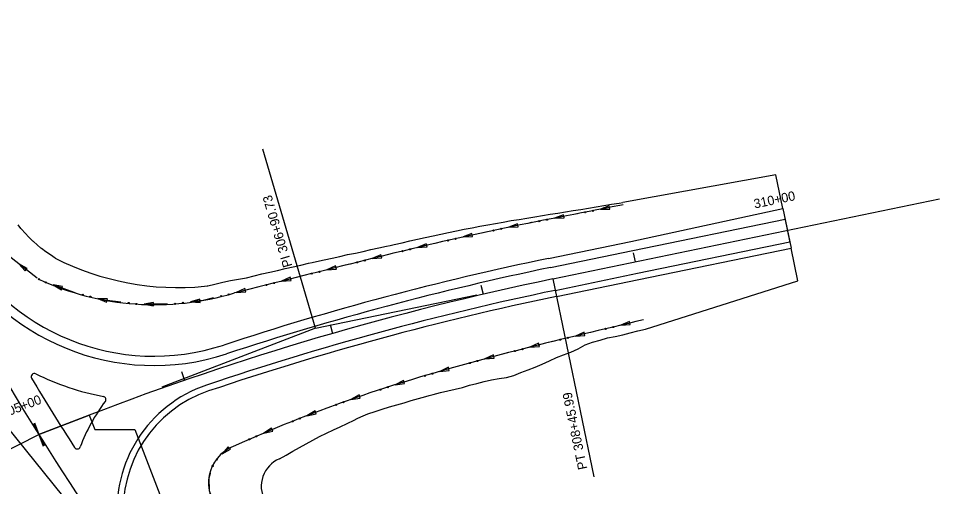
# Model space of a CAD drawing. Extents: x 916431 to 921570, y 1763982 to 1768032.
# Drawn here: x 918689 to 919282, y 1765530 to 1765831 of the extents above; entities that cross this region are included whole.
import ezdxf

# ---------------------------------------------------------------- set-up
doc = ezdxf.new("R2010")
doc.units = 0
for name, color, linetype in [('R_Horz Alg', 7, 'Continuous'), ('R_Horz Alg Annot', 7, 'Continuous'), ('R_Horz Alg Stationing', 7, 'Continuous'), ('R_Proposed Const Limits', 7, 'Continuous'), ('R_Proposed Road', 7, 'Continuous'), ('R_Shld', 7, 'Continuous'), ('R_Special Ditch', 7, 'Continuous')]:
    doc.layers.add(name, color=color, linetype=linetype)

msp = doc.modelspace()

# ---------------------------------------------------------------- linework, layer by layer
at = {"layer": 'R_Horz Alg'}
for p, q in [((919033.19, 1765663.38), (919281.92, 1765714.9)), ((919033.19, 1765663.38), (919281.92, 1765714.9)), ((918734.93, 1765575.77), (918702.47, 1765563.28)), ((918702.47, 1765563.28), (918734.93, 1765575.77)), ((918519.58, 1765470.12), (918702.47, 1765563.28))]:
    msp.add_line(p, q, dxfattribs=at)
for centre, radius, start, end in [((920196.91, 1766498.5), 1762.95, 202.25028, 218.97694), ((919420.56, 1763793.22), 1909.86, 101.70222, 111.03833), ((919420.56, 1763793.22), 1909.86, 101.70222, 111.03833)]:
    msp.add_arc(centre, radius, start, end, dxfattribs=at)
at = {"layer": 'R_Horz Alg Annot'}
for p, q in [((918880.48, 1765631.75), (918984.23, 1765653.24)), ((918880.48, 1765631.75), (918781.6, 1765593.72)), ((918663.37, 1765591.08), (918777.08, 1765450.54)), ((918738.47, 1765566.58), (918764.29, 1765566.55))]:
    msp.add_line(p, q, dxfattribs=at)
for points in [[(918880.48, 1765631.75), (918846.66, 1765746.89)], [(919033.19, 1765663.38), (919059.56, 1765536.08)], [(918734.93, 1765575.77), (918738.47, 1765566.58)], [(918764.29, 1765566.55), (918803.28, 1765465.17)]]:
    msp.add_lwpolyline(points, dxfattribs=at)
at = {"layer": 'R_Horz Alg Stationing'}
for points in [[(919182.38, 1765702.45), (919185.63, 1765686.78)], [(919084.86, 1765680.21), (919086.08, 1765674.34)], [(918986.92, 1765659.36), (918988.28, 1765653.51)], [(918889.85, 1765634.1), (918891.51, 1765628.34)], [(918794.23, 1765603.81), (918796.19, 1765598.14)], [(918698.84, 1765570.41), (918706.1, 1765556.15)], [(918698.84, 1765570.41), (918706.1, 1765556.15)], [(918699.6, 1765570.75), (918705.34, 1765555.81)]]:
    msp.add_lwpolyline(points, dxfattribs=at)
at = {"layer": 'R_Proposed Const Limits'}
for points in [[(919181.08, 1765708.75), (919176.59, 1765730.4), (919078.16, 1765712.56)], [(918809.02, 1765658.63), (918810.71, 1765658.93), (918811.18, 1765659.01), (918815.77, 1765659.98), (918820.76, 1765661.25), (918825.76, 1765662.47), (918830.88, 1765663.32), (918835.98, 1765664.19), (918840.99, 1765665.39), (918845.99, 1765666.57), (918851, 1765667.74), (918856, 1765668.9), (918861.02, 1765670.02), (918866.05, 1765671.1), (918871.05, 1765672.26), (918876.05, 1765673.42), (918878.36, 1765673.96), (918881.06, 1765674.54), (918886.08, 1765675.61), (918891.09, 1765676.73), (918896.08, 1765677.88), (918901.09, 1765679.01), (918906.11, 1765680.05), (918911.12, 1765681.13), (918916.11, 1765682.28), (918921.11, 1765683.41), (918926.13, 1765684.42), (918928.46, 1765684.89), (918931.15, 1765685.45), (918936.13, 1765686.63), (918941.12, 1765687.79), (918946.1, 1765688.95), (918951.09, 1765690.1), (918956.09, 1765691.2), (918961.09, 1765692.26), (918966.11, 1765693.29), (918971.12, 1765694.32), (918976.13, 1765695.35), (918981.16, 1765696.31), (918986.19, 1765697.24), (918991.22, 1765698.16), (918996.25, 1765699.09), (919001.29, 1765700), (919006.33, 1765700.86), (919011.38, 1765701.69), (919016.43, 1765702.49), (919021.48, 1765703.31), (919026.48, 1765704.17), (919031.43, 1765704.94), (919036.37, 1765705.72), (919041.3, 1765706.59), (919046.25, 1765707.36), (919051.19, 1765708.14), (919056.14, 1765708.91), (919061.08, 1765709.69), (919066.01, 1765710.57), (919070.94, 1765711.38), (919075.89, 1765712.16), (919078.16, 1765712.56)], [(918712.98, 1765676.7), (918709.98, 1765678.79), (918707, 1765680.88), (918704.12, 1765683.06), (918703.88, 1765683.26), (918701.35, 1765685.34), (918698.96, 1765687.44), (918698.67, 1765687.71), (918697.62, 1765688.69), (918696.93, 1765689.35), (918696.09, 1765690.17), (918693.64, 1765692.74), (918691.36, 1765695.44), (918691.02, 1765695.87), (918689.16, 1765698.2)], [(919092.67, 1765631.15), (919190.74, 1765662.1), (919186.38, 1765683.16)], [(918857.26, 1765547.56), (918861.53, 1765550.06), (918865.81, 1765552.55), (918870.12, 1765554.93), (918874.46, 1765557.27), (918878.76, 1765559.72), (918883.12, 1765562), (918887.54, 1765564.12), (918891.97, 1765566.21), (918896.41, 1765568.28), (918900.86, 1765570.33), (918905.29, 1765572.46), (918907.32, 1765573.5), (918909.69, 1765574.71), (918914.2, 1765576.56), (918918.82, 1765578.06), (918923.44, 1765579.57), (918928.04, 1765581.16), (918932.74, 1765582.38), (918937.4, 1765583.74), (918942.06, 1765585.12), (918946.73, 1765586.45), (918951.4, 1765587.77), (918953.57, 1765588.37), (918956.08, 1765589.06), (918960.78, 1765590.29), (918965.51, 1765591.39), (918970.25, 1765592.47), (918974.97, 1765593.61), (918979.62, 1765595.01), (918984.33, 1765596.2), (918989.05, 1765597.36), (918993.78, 1765598.47), (918998.59, 1765599.23), (919003.4, 1765599.98), (919008.06, 1765601.35), (919012.63, 1765603.18), (919017.24, 1765604.81), (919021.82, 1765606.64), (919026.35, 1765608.64), (919030.89, 1765610.68), (919035.4, 1765612.87), (919040.02, 1765614.58), (919044.7, 1765616.22), (919049.33, 1765618.5), (919053.94, 1765620.89), (919058.66, 1765622.78), (919063.52, 1765623.94), (919068.31, 1765625.48), (919073.22, 1765626.41), (919078.13, 1765627.36), (919082.97, 1765628.68), (919087.82, 1765629.9), (919092.67, 1765631.15)]]:
    msp.add_lwpolyline(points, dxfattribs=at)
for centre, radius, start, end in [((918792.18, 1765833.37), 175.55, 243.17977, 275.50176), ((918864.61, 1765529.99), 19.05, 112.67795, 208.20547)]:
    msp.add_arc(centre, radius, start, end, dxfattribs=at)
at = {"layer": 'R_Proposed Road'}
for p, q in [((919181.08, 1765708.75), (919186.38, 1765683.16)), ((919084.56, 1765681.68), (919182.49, 1765701.93)), ((919087.6, 1765666.99), (919185.52, 1765687.28)), ((919031.67, 1765670.72), (919084.56, 1765681.68)), ((919034.71, 1765656.04), (919087.6, 1765666.99))]:
    msp.add_line(p, q, dxfattribs=at)
for centre, radius, start, end in [((918776.54, 1765757.7), 150, 207.5444, 288.15084), ((919420.56, 1763793.22), 1917.36, 101.70222, 108.15084), ((919420.56, 1763793.22), 1902.36, 101.70222, 108.70584), ((918699.58, 1765600.53), 2, 63.91293, 210.9518), ((918776.54, 1765757.7), 173, 243.91293, 259.1681), ((920196.91, 1766498.5), 1747.95, 210.9518, 212.67226), ((918837.71, 1765514.58), 85, 108.70584, 185.72161), ((918837.71, 1765514.58), 116, 142.86085, 159.45924), ((918743.65, 1765585.82), 2, 322.86085, 79.1681), ((918727.22, 1765555.98), 2, 212.67226, 339.45924)]:
    msp.add_arc(centre, radius, start, end, dxfattribs=at)
at = {"layer": 'R_Shld'}
for p, q in [((919083.34, 1765687.55), (919181.08, 1765708.75)), ((919030.45, 1765676.6), (919083.34, 1765687.55)), ((919088.41, 1765663.07), (919186.38, 1765683.16)), ((919035.52, 1765652.12), (919088.41, 1765663.07))]:
    msp.add_line(p, q, dxfattribs=at)
for centre, radius, start, end in [((918776.54, 1765757.7), 144, 207.5444, 288.15084), ((919420.56, 1763793.22), 1923.36, 101.70222, 108.15084), ((919420.56, 1763793.22), 1898.36, 101.70222, 108.70584), ((918837.71, 1765514.58), 81, 108.70584, 185.00335)]:
    msp.add_arc(centre, radius, start, end, dxfattribs=at)
at = {"layer": 'R_Special Ditch'}
for p, q in [((919069.44, 1765710.39), (919063.75, 1765708.2)), ((919069.84, 1765708.31), (919069.44, 1765710.39)), ((919039.95, 1765704.66), (919034.26, 1765702.48)), ((919040.35, 1765702.58), (919039.95, 1765704.66)), ((919063.75, 1765708.2), (919069.84, 1765708.31)), ((919010.47, 1765698.87), (919004.8, 1765696.64)), ((919004.8, 1765696.64), (919010.89, 1765696.79)), ((919010.89, 1765696.79), (919010.47, 1765698.87)), ((919034.26, 1765702.48), (919040.35, 1765702.58)), ((918981.06, 1765692.68), (918975.42, 1765690.36)), ((918981.51, 1765690.61), (918981.06, 1765692.68)), ((918951.75, 1765686.03), (918946.15, 1765683.62)), ((918952.23, 1765683.97), (918951.75, 1765686.03)), ((918975.42, 1765690.36), (918981.51, 1765690.61)), ((918946.15, 1765683.62), (918952.23, 1765683.97)), ((918689.7, 1765673.06), (918693.77, 1765668.53)), ((918695.08, 1765670.19), (918689.7, 1765673.06)), ((918922.54, 1765678.95), (918916.97, 1765676.48)), ((918916.97, 1765676.48), (918923.05, 1765676.89)), ((918923.05, 1765676.89), (918922.54, 1765678.95)), ((918693.77, 1765668.53), (918695.08, 1765670.19)), ((918893.39, 1765671.71), (918887.82, 1765669.24)), ((918887.82, 1765669.24), (918893.9, 1765669.66)), ((918893.9, 1765669.66), (918893.39, 1765671.71)), ((918864.24, 1765664.44), (918858.68, 1765661.96)), ((918858.68, 1765661.96), (918864.76, 1765662.39)), ((918864.76, 1765662.39), (918864.24, 1765664.44)), ((918711.75, 1765659.49), (918717.03, 1765656.46)), ((918717.75, 1765658.45), (918711.75, 1765659.49)), ((918717.03, 1765656.46), (918717.75, 1765658.45)), ((918835.1, 1765657.14), (918829.54, 1765654.65)), ((918835.62, 1765655.09), (918835.1, 1765657.14)), ((918740.47, 1765650.89), (918746.07, 1765648.48)), ((918746.56, 1765650.54), (918740.47, 1765650.89)), ((918746.07, 1765648.48), (918746.56, 1765650.54)), ((918806, 1765650.36), (918800.16, 1765648.61)), ((918806.24, 1765648.26), (918806, 1765650.36)), ((918829.54, 1765654.65), (918835.62, 1765655.09)), ((918776.21, 1765648.18), (918770.21, 1765647.11)), ((918770.21, 1765647.11), (918776.21, 1765646.06)), ((918776.21, 1765646.06), (918776.21, 1765648.18)), ((918800.16, 1765648.61), (918806.24, 1765648.26)), ((919082.44, 1765636.02), (919076.85, 1765633.6)), ((919076.85, 1765633.6), (919082.93, 1765633.96)), ((919082.93, 1765633.96), (919082.44, 1765636.02)), ((919053.22, 1765629.06), (919047.63, 1765626.64)), ((919047.63, 1765626.64), (919053.71, 1765627)), ((919053.71, 1765627), (919053.22, 1765629.06)), ((919024.01, 1765622), (919018.45, 1765619.52)), ((919018.45, 1765619.52), (919024.52, 1765619.95)), ((919024.52, 1765619.95), (919024.01, 1765622)), ((918994.9, 1765614.51), (918989.38, 1765611.94)), ((918995.45, 1765612.47), (918994.9, 1765614.51)), ((918989.38, 1765611.94), (918995.45, 1765612.47)), ((918965.92, 1765606.55), (918960.44, 1765603.89)), ((918960.44, 1765603.89), (918966.5, 1765604.51)), ((918966.5, 1765604.51), (918965.92, 1765606.55)), ((918937.08, 1765598.08), (918931.66, 1765595.29)), ((918931.66, 1765595.29), (918937.71, 1765596.06)), ((918937.71, 1765596.06), (918937.08, 1765598.08)), ((918908.48, 1765588.77), (918903.16, 1765585.8)), ((918903.16, 1765585.8), (918909.18, 1765586.77)), ((918909.18, 1765586.77), (918908.48, 1765588.77)), ((918880.2, 1765578.56), (918874.98, 1765575.42)), ((918880.96, 1765576.58), (918880.2, 1765578.56)), ((918874.98, 1765575.42), (918880.96, 1765576.58)), ((918852.25, 1765567.45), (918847.13, 1765564.15)), ((918853.08, 1765565.5), (918852.25, 1765567.45)), ((918847.13, 1765564.15), (918853.08, 1765565.5)), ((918824.35, 1765555.48), (918820.36, 1765550.88)), ((918825.69, 1765553.84), (918824.35, 1765555.48)), ((918820.36, 1765550.88), (918825.69, 1765553.84))]:
    msp.add_line(p, q, dxfattribs=at)
for points in [[(919078.47, 1765711.06), (919076.21, 1765710.62), (919071.3, 1765709.67), (919066.39, 1765708.72), (919061.48, 1765707.76), (919056.57, 1765706.81), (919051.66, 1765705.86), (919046.75, 1765704.9), (919041.85, 1765703.95), (919036.94, 1765703), (919032.03, 1765702.04), (919027.12, 1765701.09), (919022.15, 1765700.12), (919017.14, 1765699.13), (919012.14, 1765698.13), (919007.14, 1765697.11), (919002.15, 1765696.08), (918997.15, 1765695.04), (918992.16, 1765693.99), (918987.17, 1765692.92), (918982.19, 1765691.84), (918977.2, 1765690.75), (918972.22, 1765689.64), (918967.25, 1765688.52), (918962.27, 1765687.39), (918957.3, 1765686.24), (918952.33, 1765685.08), (918947.36, 1765683.91), (918942.4, 1765682.72), (918937.44, 1765681.52), (918932.48, 1765680.31), (918929.82, 1765679.66), (918927.53, 1765679.09), (918922.57, 1765677.86), (918917.62, 1765676.64), (918912.66, 1765675.41), (918907.71, 1765674.18), (918902.75, 1765672.95), (918897.8, 1765671.72), (918892.84, 1765670.49), (918887.89, 1765669.25), (918882.93, 1765668.02), (918880.26, 1765667.35), (918877.97, 1765666.78), (918873.01, 1765665.54), (918868.05, 1765664.31), (918863.09, 1765663.07), (918858.13, 1765661.83), (918853.17, 1765660.58), (918848.21, 1765659.34), (918843.24, 1765658.09), (918838.28, 1765656.85), (918833.31, 1765655.6), (918828.34, 1765654.35)], [(919078.47, 1765711.06), (919076.21, 1765710.62), (919071.3, 1765709.67), (919066.39, 1765708.72), (919063.75, 1765708.2)], [(919048.99, 1765705.34), (919046.75, 1765704.9), (919041.85, 1765703.95), (919036.94, 1765703), (919034.26, 1765702.48)], [(919049.02, 1765705.34), (919048.99, 1765705.34)], [(919019.5, 1765699.6), (919017.14, 1765699.13), (919012.14, 1765698.13), (919007.14, 1765697.11), (919004.8, 1765696.63)], [(919019.54, 1765699.6), (919019.5, 1765699.6)], [(918990.08, 1765693.54), (918987.17, 1765692.92), (918982.19, 1765691.84), (918977.2, 1765690.75), (918975.42, 1765690.35)], [(918990.12, 1765693.55), (918990.08, 1765693.54)], [(918960.76, 1765687.04), (918957.3, 1765686.24), (918952.33, 1765685.08), (918947.36, 1765683.91), (918946.15, 1765683.62)], [(918960.79, 1765687.05), (918960.76, 1765687.04)], [(918931.54, 1765680.08), (918929.82, 1765679.66), (918927.53, 1765679.09), (918922.57, 1765677.86), (918917.62, 1765676.64), (918916.97, 1765676.48)], [(918931.57, 1765680.09), (918931.54, 1765680.08)], [(918701.52, 1765663.82), (918682.87, 1765678.39)], [(918701.52, 1765663.82), (918689.7, 1765673.06)], [(918902.38, 1765672.86), (918897.8, 1765671.72), (918892.84, 1765670.49), (918887.89, 1765669.25), (918887.82, 1765669.24)], [(918902.42, 1765672.87), (918902.38, 1765672.86)], [(918702.42, 1765663.25), (918702.42, 1765663.25)], [(918873.23, 1765665.6), (918873.01, 1765665.54), (918868.05, 1765664.31), (918863.09, 1765663.07), (918858.68, 1765661.96)], [(918873.27, 1765665.61), (918873.23, 1765665.6)], [(918725.85, 1765654.39), (918711.75, 1765659.49)], [(918844.09, 1765658.31), (918843.24, 1765658.09), (918838.28, 1765656.85), (918833.31, 1765655.6), (918829.54, 1765654.65)], [(918844.13, 1765658.32), (918844.09, 1765658.31)], [(918725.89, 1765654.38), (918725.85, 1765654.39)], [(918755.25, 1765648.46), (918746.49, 1765649.47), (918740.47, 1765650.89)], [(918814.92, 1765651.15), (918808.23, 1765649.56), (918800.16, 1765648.61)], [(918814.96, 1765651.16), (918814.92, 1765651.15)], [(918755.29, 1765648.46), (918755.25, 1765648.46)], [(918785.21, 1765647.13), (918770.21, 1765647.11)], [(918785.25, 1765647.13), (918785.21, 1765647.13)], [(919091.44, 1765637.08), (919086.57, 1765635.92), (919081.71, 1765634.76), (919076.84, 1765633.6), (919071.98, 1765632.44), (919067.11, 1765631.28), (919062.24, 1765630.12), (919057.38, 1765628.96), (919052.51, 1765627.8), (919047.65, 1765626.64), (919042.78, 1765625.48), (919037.98, 1765624.33), (919033.22, 1765623.18), (919028.46, 1765622.01), (919023.71, 1765620.84), (919018.96, 1765619.64), (919014.21, 1765618.44), (919009.46, 1765617.23), (919004.72, 1765616), (918999.98, 1765614.76), (918995.25, 1765613.51), (918990.52, 1765612.24), (918985.8, 1765610.97), (918981.07, 1765609.68), (918976.35, 1765608.38), (918971.64, 1765607.06), (918966.93, 1765605.74), (918962.22, 1765604.4), (918957.52, 1765603.05), (918952.82, 1765601.69), (918950.29, 1765600.95), (918948.12, 1765600.31), (918943.44, 1765598.91), (918938.76, 1765597.49), (918934.08, 1765596.04), (918929.42, 1765594.57), (918924.76, 1765593.08), (918920.11, 1765591.56), (918915.46, 1765590.02), (918910.83, 1765588.45), (918906.2, 1765586.86), (918903.72, 1765585.99), (918901.58, 1765585.24), (918896.97, 1765583.61), (918892.37, 1765581.95), (918887.78, 1765580.26), (918883.2, 1765578.55), (918878.62, 1765576.82), (918874.05, 1765575.06), (918869.5, 1765573.28), (918864.95, 1765571.48), (918860.41, 1765569.65), (918855.88, 1765567.8), (918851.36, 1765565.93), (918846.85, 1765564.03), (918842.77, 1765562.29), (918842.36, 1765562.11), (918840.87, 1765561.47), (918837.87, 1765560.17), (918833.39, 1765558.21), (918828.92, 1765556.22), (918824.46, 1765554.21)], [(919091.44, 1765637.08), (919086.57, 1765635.92), (919081.71, 1765634.76), (919076.85, 1765633.6)], [(919062.22, 1765630.12), (919057.38, 1765628.96), (919052.51, 1765627.8), (919047.65, 1765626.64), (919047.63, 1765626.64)], [(919062.26, 1765630.12), (919062.24, 1765630.12), (919062.22, 1765630.12)], [(919033.01, 1765623.13), (919028.46, 1765622.01), (919023.71, 1765620.84), (919018.96, 1765619.64), (919018.45, 1765619.52)], [(919033.04, 1765623.14), (919033.01, 1765623.13)], [(919003.88, 1765615.78), (918999.98, 1765614.76), (918995.25, 1765613.51), (918990.52, 1765612.24), (918989.38, 1765611.93)], [(919003.92, 1765615.79), (919003.88, 1765615.78)], [(918974.88, 1765607.96), (918971.64, 1765607.06), (918966.93, 1765605.74), (918962.22, 1765604.4), (918960.44, 1765603.89)], [(918974.91, 1765607.97), (918974.88, 1765607.96)], [(918946.01, 1765599.68), (918943.44, 1765598.91), (918938.76, 1765597.49), (918934.08, 1765596.04), (918931.67, 1765595.28)], [(918946.04, 1765599.69), (918946.01, 1765599.68)], [(918917.36, 1765590.65), (918915.46, 1765590.02), (918910.83, 1765588.45), (918906.2, 1765586.86), (918903.72, 1765585.99), (918903.16, 1765585.8)], [(918917.4, 1765590.66), (918917.36, 1765590.65)], [(918889.01, 1765580.71), (918887.78, 1765580.26), (918883.2, 1765578.55), (918878.62, 1765576.82), (918874.98, 1765575.42)], [(918889.05, 1765580.73), (918889.01, 1765580.71)], [(918860.99, 1765569.89), (918860.41, 1765569.65), (918855.88, 1765567.8), (918851.36, 1765565.93), (918847.13, 1765564.15)], [(918861.03, 1765569.9), (918860.99, 1765569.89)], [(918833.33, 1765558.18), (918828.92, 1765556.22), (918824.46, 1765554.21), (918820.36, 1765550.88)], [(918833.37, 1765558.2), (918833.33, 1765558.18)], [(918812.74, 1765538.29), (918811.82, 1765535.12), (918812.02, 1765527.25), (918813.25, 1765523.63)], [(918812.75, 1765538.33), (918812.74, 1765538.29)]]:
    msp.add_lwpolyline(points, dxfattribs=at)
for centre in [(919053.92, 1765706.26), (919058.84, 1765707.21), (919024.44, 1765700.53), (919029.35, 1765701.49), (918995, 1765694.55), (918999.9, 1765695.58), (918965.66, 1765688.12), (918970.55, 1765689.22), (918936.42, 1765681.24), (918941.29, 1765682.42), (918907.26, 1765674.03), (918912.12, 1765675.24), (918878.11, 1765666.78), (918882.97, 1765667.99), (918702.45, 1765663.2), (918707.03, 1765661.16), (918848.97, 1765659.49), (918853.83, 1765660.71), (918730.71, 1765653.15), (918735.59, 1765652), (918819.81, 1765652.28), (918824.69, 1765653.44), (918760.24, 1765647.85), (918765.21, 1765647.28), (918790.22, 1765647.4), (918795.19, 1765647.98), (919067.11, 1765631.24), (919071.99, 1765632.41), (919042.77, 1765625.44), (919037.9, 1765624.27), (919008.75, 1765617), (919013.6, 1765618.25), (918979.73, 1765609.27), (918984.56, 1765610.59), (918955.64, 1765602.47), (918950.83, 1765601.07), (918922.14, 1765592.18), (918926.91, 1765593.73), (918898.46, 1765584.09), (918893.74, 1765582.4), (918870.33, 1765573.57), (918865.67, 1765571.73), (918837.95, 1765560.17), (918842.54, 1765562.16), (918814.28, 1765543.04), (918817.04, 1765547.22)]:
    msp.add_circle(centre, 0.375, dxfattribs=at)
for centre, radius, start, end in [((918777.11, 1765824.84), 178.02, 245.19141, 286.72535), ((918837.55, 1765531.81), 25.94, 120.31472, 230.76638)]:
    msp.add_arc(centre, radius, start, end, dxfattribs=at)

# ---------------------------------------------------------------- texts
at = {"layer": 'R_Horz Alg Annot'}
for s, rotation, p in [('PI 306+90.73', 106.37028, (918865.59, 1765671.8)), ('PT 308+45.99', 101.70222, (919055.4, 1765541.35))]:
    msp.add_text(s, height=6, rotation=rotation, dxfattribs=at).set_placement(p)
at = {"layer": 'R_Horz Alg Stationing'}
for s, rotation, p in [('310+00', 11.70222, (919163.07, 1765708.66)), ('305+00', 21.03833, (918679.54, 1765573.75))]:
    msp.add_text(s, height=6, rotation=rotation, dxfattribs=at).set_placement(p)

doc.saveas('drawing.dxf')
